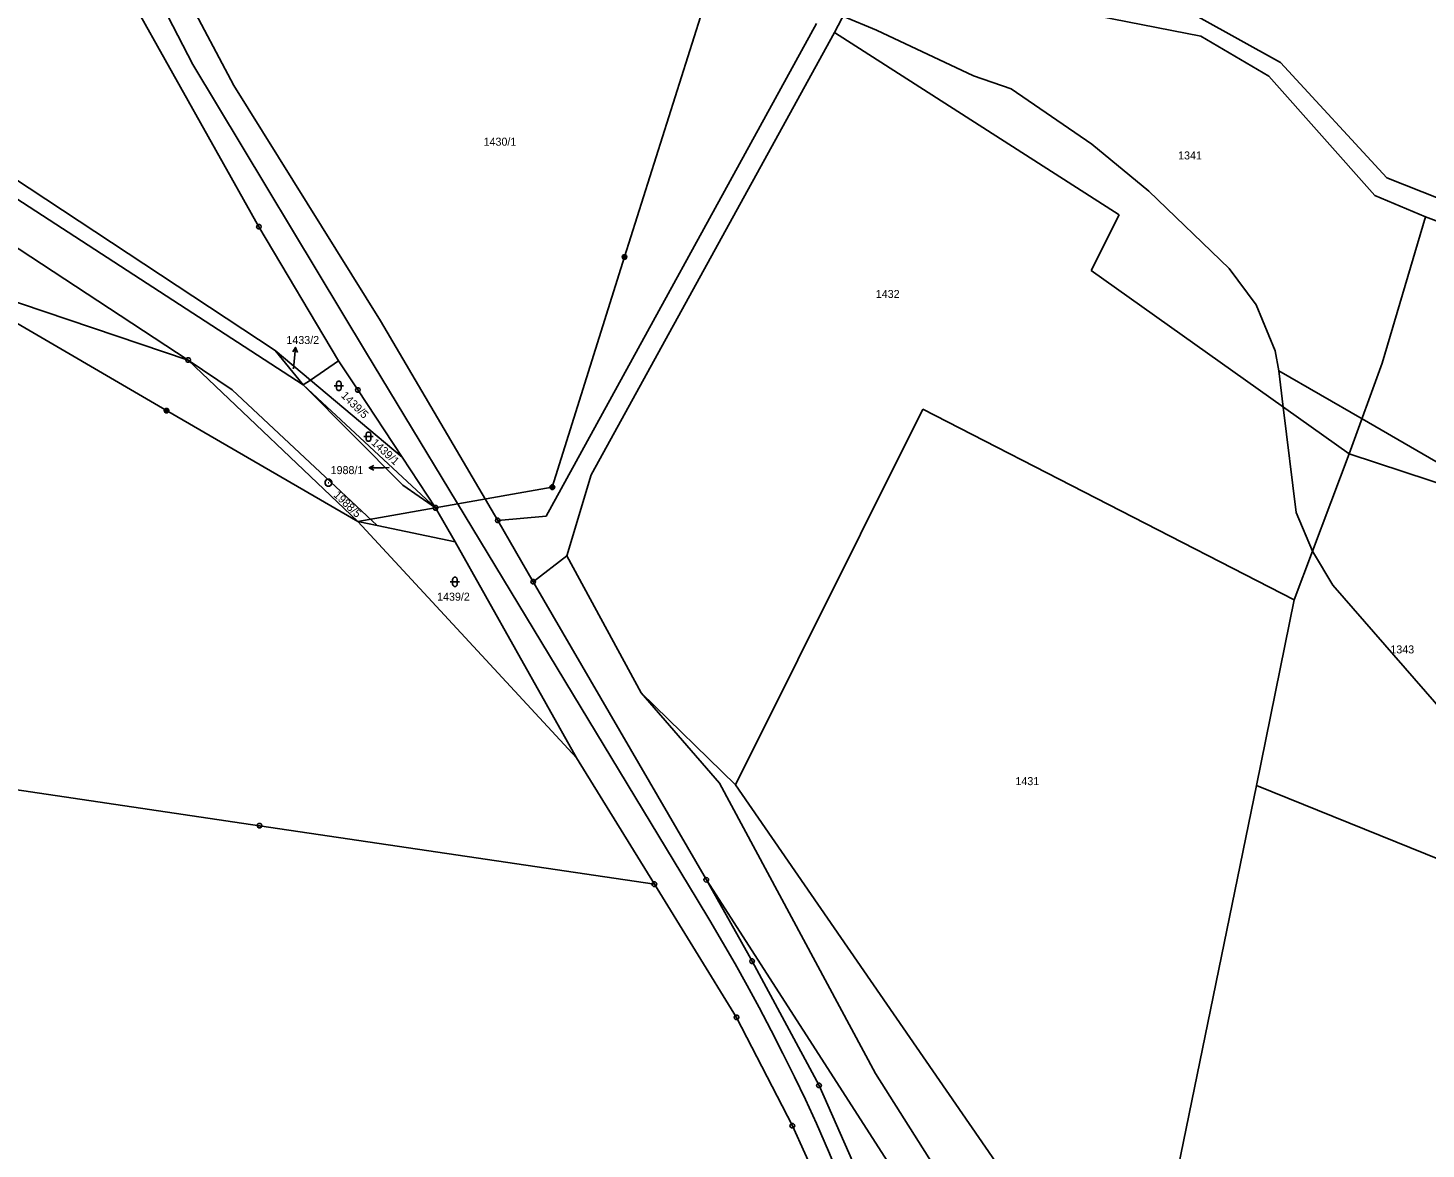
# Model space of a CAD drawing. Extents: x -789470 to -786707, y -1118640 to -1114455.
# Drawn here: x -787308.1 to -787011.1, y -1117950.7 to -1117712.5 of the extents above; entities that cross this region are included whole.
import ezdxf

# ---------------------------------------------------------------- set-up
doc = ezdxf.new("R2010")
doc.units = 0
for name, color, linetype in [('1', 7, 'Continuous'), ('11', 7, 'Continuous'), ('2', 7, 'Continuous'), ('3', 7, 'Continuous'), ('6', 7, 'Continuous'), ('7', 7, 'Continuous'), ('8', 7, 'Continuous')]:
    doc.layers.add(name, color=color, linetype=linetype)

msp = doc.modelspace()

# ---------------------------------------------------------------- linework, layer by layer
at = {"layer": '1'}
for p, q in [((-787264.39, -1117724.76), (-787281.5, -1117692.34)), ((-787291.42, -1117697.04), (-787259.05, -1117754.75)), ((-787130.82, -1117702.16), (-787136.77, -1117713.49)), ((-787058.93, -1117714.23), (-787093.33, -1117707.53)), ((-787140.62, -1117711.53), (-787198, -1117816.22)), ((-787059.5, -1117710.17), (-787042.03, -1117719.84)), ((-787188.44, -1117807.41), (-787136.77, -1117713.49)), ((-787136.77, -1117713.49), (-787076.27, -1117752.22)), ((-787044.49, -1117722.72), (-787058.93, -1117714.23)), ((-787042.03, -1117719.84), (-787019.38, -1117744.35)), ((-787021.94, -1117748.11), (-787044.49, -1117722.72)), ((-787255.59, -1117781.03), (-787341.85, -1117724.21)), ((-787233.24, -1117774.71), (-787264.39, -1117724.76)), ((-787249.62, -1117788.3), (-787339.28, -1117730.12)), ((-787334.34, -1117743.57), (-787274.1, -1117783.05)), ((-787019.38, -1117744.35), (-786937.83, -1117776.81)), ((-787011.2, -1117752.61), (-787021.94, -1117748.11)), ((-787076.27, -1117752.22), (-787082.23, -1117764.04)), ((-787020.37, -1117783.74), (-787011.2, -1117752.61)), ((-786970.08, -1117768.29), (-787011.2, -1117752.61)), ((-787259.05, -1117754.75), (-787242.15, -1117783.25)), ((-787329.24, -1117764.44), (-787274.1, -1117783.05)), ((-787082.23, -1117764.04), (-787027.4, -1117802.98)), ((-787208.31, -1117817.12), (-787233.24, -1117774.71)), ((-787274.1, -1117783.05), (-787264.76, -1117789.41)), ((-787274.1, -1117783.05), (-787238.04, -1117817.33)), ((-787255.59, -1117781.03), (-787249.62, -1117788.3)), ((-787248.13, -1117787.29), (-787255.59, -1117781.03)), ((-787242.15, -1117783.25), (-787248.13, -1117787.29)), ((-787242.15, -1117783.25), (-787238.02, -1117789.4)), ((-787027.4, -1117802.98), (-787020.37, -1117783.74)), ((-787248.13, -1117787.29), (-787249.62, -1117788.3)), ((-787228.5, -1117809.63), (-787249.62, -1117788.3)), ((-787221.52, -1117814.46), (-787249.62, -1117788.3)), ((-787228.62, -1117803.68), (-787248.13, -1117787.29)), ((-787264.76, -1117789.41), (-787233.93, -1117818.2)), ((-787238.02, -1117789.4), (-787228.62, -1117803.68)), ((-787157.82, -1117873.26), (-787118.02, -1117793.52)), ((-787118.02, -1117793.52), (-787039.1, -1117834.01)), ((-787228.62, -1117803.68), (-787221.52, -1117814.46)), ((-787039.1, -1117834.01), (-787027.4, -1117802.98)), ((-787027.4, -1117802.98), (-786983.7, -1117817.36)), ((-787221.52, -1117814.46), (-787228.5, -1117809.63)), ((-787193.66, -1117824.64), (-787188.44, -1117807.41)), ((-787221.52, -1117814.46), (-787217.39, -1117821.69)), ((-787191.61, -1117867.54), (-787238.04, -1117817.33)), ((-787238.04, -1117817.33), (-787233.93, -1117818.2)), ((-787233.93, -1117818.2), (-787217.39, -1117821.69)), ((-787198, -1117816.22), (-787208.31, -1117817.12)), ((-787200.76, -1117830.15), (-787208.31, -1117817.12)), ((-787217.39, -1117821.69), (-787191.61, -1117867.54)), ((-787200.76, -1117830.15), (-787193.66, -1117824.64)), ((-787193.66, -1117824.64), (-787177.84, -1117853.72)), ((-787163.99, -1117893.46), (-787200.76, -1117830.15)), ((-787047.08, -1117873.45), (-787039.1, -1117834.01)), ((-787177.84, -1117853.72), (-787161.21, -1117872.93)), ((-787177.84, -1117853.72), (-787157.82, -1117873.26)), ((-787175.04, -1117894.4), (-787191.61, -1117867.54)), ((-787342.81, -1117869.52), (-787258.93, -1117881.96)), ((-787161.21, -1117872.93), (-787128.04, -1117934.59)), ((-787157.82, -1117873.26), (-787077.39, -1117989.76)), ((-787071.15, -1117990.73), (-787047.08, -1117873.45)), ((-787047.08, -1117873.45), (-787004.56, -1117890.66)), ((-787175.04, -1117894.4), (-787258.93, -1117881.96)), ((-787157.56, -1117922.69), (-787175.04, -1117894.4)), ((-787163.99, -1117893.46), (-787091.23, -1118006.46)), ((-787154.27, -1117910.76), (-787163.99, -1117893.46)), ((-787140.05, -1117937.14), (-787154.27, -1117910.76)), ((-787145.72, -1117945.71), (-787157.56, -1117922.69)), ((-787128.04, -1117934.59), (-787083.58, -1118004.78)), ((-787131.85, -1117955.61), (-787140.05, -1117937.14)), ((-787135.71, -1117967.62), (-787145.72, -1117945.71))]:
    msp.add_line(p, q, dxfattribs=at)
at = {"layer": '11'}
for points in [[(-787134.96, -1117710.03), (-787127.81, -1117712.99), (-787107.23, -1117722.71), (-787099.24, -1117725.42), (-787082.09, -1117737.18), (-787070, -1117747.16), (-787052.94, -1117763.57), (-787047.15, -1117771.3), (-787043.1, -1117781.11), (-787042.34, -1117785.36)], [(-787042.34, -1117785.36), (-787024.68, -1117795.55), (-786991.12, -1117814.92), (-786984.15, -1117818.94), (-786981.58, -1117820.43), (-786936.16, -1117838.26), (-786913.37, -1117842.53), (-786900.27, -1117844.49), (-786842.47, -1117856.66), (-786829.42, -1117861.15), (-786821.6, -1117864.46), (-786814.71, -1117867.37), (-786798.67, -1117876.14)], [(-787042.34, -1117785.36), (-787041.4, -1117793.03), (-787038.67, -1117815.46), (-787035.18, -1117823.62), (-787035.02, -1117823.99), (-787030.91, -1117830.84), (-787006.87, -1117858.4), (-786998.03, -1117867.71), (-786979.04, -1117887.72), (-786975.32, -1117892.87), (-786971.98, -1117895.48), (-786967.44, -1117901.49), (-786952.89, -1117916.16), (-786931.6, -1117932.67), (-786922.44, -1117941.31), (-786915.44, -1117951.6)]]:
    msp.add_lwpolyline(points, dxfattribs=at)
at = {"layer": '3'}
for points in [[(-787243.08, -1117788.54), (-787241.81, -1117788.54), (-787241.08, -1117788.54)], [(-787236.79, -1117799.32), (-787235.52, -1117799.32), (-787234.79, -1117799.32)], [(-787218.41, -1117830.17), (-787217.14, -1117830.17), (-787216.41, -1117830.17)]]:
    msp.add_lwpolyline(points, dxfattribs=at)
for points in [[(-787242.58, -1117788.04), (-787242.48, -1117787.75), (-787242.23, -1117787.57), (-787241.92, -1117787.57), (-787241.67, -1117787.75), (-787241.57, -1117788.04), (-787241.57, -1117789.04), (-787241.67, -1117789.33), (-787241.92, -1117789.51), (-787242.23, -1117789.51), (-787242.48, -1117789.33), (-787242.58, -1117789.04)], [(-787236.29, -1117798.82), (-787236.19, -1117798.53), (-787235.94, -1117798.35), (-787235.63, -1117798.35), (-787235.38, -1117798.53), (-787235.28, -1117798.82), (-787235.28, -1117799.82), (-787235.38, -1117800.11), (-787235.63, -1117800.29), (-787235.94, -1117800.29), (-787236.19, -1117800.11), (-787236.29, -1117799.82)], [(-787217.91, -1117829.67), (-787217.81, -1117829.38), (-787217.56, -1117829.2), (-787217.25, -1117829.2), (-787217, -1117829.38), (-787216.9, -1117829.67), (-787216.9, -1117830.67), (-787217, -1117830.96), (-787217.25, -1117831.14), (-787217.56, -1117831.14), (-787217.81, -1117830.96), (-787217.91, -1117830.67)]]:
    msp.add_lwpolyline(points, close=True, dxfattribs=at)
at = {"layer": '6'}
for p, q in [((-787273.09, -1117720.29), (-787286.26, -1117694.67)), ((-787163.64, -1117705.03), (-787181.38, -1117761.15)), ((-787236.23, -1117781.6), (-787273.09, -1117720.29)), ((-787196.72, -1117810.06), (-787181.38, -1117761.15)), ((-787278.7, -1117793.79), (-787320.68, -1117769.26)), ((-787236.23, -1117781.6), (-787208.93, -1117826.64)), ((-787238.04, -1117817.33), (-787278.7, -1117793.79)), ((-787196.72, -1117810.06), (-787238.04, -1117817.33)), ((-787165.94, -1117897.62), (-787208.93, -1117826.64))]:
    msp.add_line(p, q, dxfattribs=at)
for points in [[(-787181.53, -1117760.67), (-787181.22, -1117760.67), (-787180.97, -1117760.85), (-787180.87, -1117761.14), (-787180.97, -1117761.43), (-787181.22, -1117761.61), (-787181.53, -1117761.61), (-787181.78, -1117761.43), (-787181.88, -1117761.14), (-787181.78, -1117760.85), (-787181.53, -1117760.67), (-787181.5, -1117760.71), (-787181.26, -1117760.71), (-787181.1, -1117760.79), (-787181.66, -1117760.79), (-787181.74, -1117760.87), (-787181.02, -1117760.87), (-787181.02, -1117760.95), (-787181.74, -1117760.95), (-787181.78, -1117761.03), (-787180.98, -1117761.03), (-787180.94, -1117761.11), (-787181.82, -1117761.11), (-787181.82, -1117761.19), (-787180.94, -1117761.19), (-787180.97, -1117761.27), (-787181.78, -1117761.27), (-787181.77, -1117761.35), (-787180.96, -1117761.35), (-787181.01, -1117761.43), (-787181.73, -1117761.43), (-787181.65, -1117761.51), (-787181.09, -1117761.51), (-787181.2, -1117761.59), (-787181.54, -1117761.59)], [(-787278.85, -1117793.31), (-787278.54, -1117793.31), (-787278.29, -1117793.49), (-787278.19, -1117793.78), (-787278.29, -1117794.07), (-787278.54, -1117794.25), (-787278.85, -1117794.25), (-787279.1, -1117794.07), (-787279.2, -1117793.78), (-787279.1, -1117793.49), (-787278.85, -1117793.31), (-787278.82, -1117793.35), (-787278.58, -1117793.35), (-787278.42, -1117793.43), (-787278.98, -1117793.43), (-787279.06, -1117793.51), (-787278.34, -1117793.51), (-787278.34, -1117793.59), (-787279.06, -1117793.59), (-787279.1, -1117793.67), (-787278.3, -1117793.67), (-787278.26, -1117793.75), (-787279.14, -1117793.75), (-787279.14, -1117793.83), (-787278.26, -1117793.83), (-787278.29, -1117793.91), (-787279.1, -1117793.91), (-787279.09, -1117793.99), (-787278.28, -1117793.99), (-787278.33, -1117794.07), (-787279.05, -1117794.07), (-787278.97, -1117794.15), (-787278.41, -1117794.15), (-787278.52, -1117794.23), (-787278.86, -1117794.23)], [(-787196.87, -1117809.58), (-787196.56, -1117809.58), (-787196.31, -1117809.76), (-787196.21, -1117810.05), (-787196.31, -1117810.34), (-787196.56, -1117810.52), (-787196.87, -1117810.52), (-787197.12, -1117810.34), (-787197.22, -1117810.05), (-787197.12, -1117809.76), (-787196.87, -1117809.58), (-787196.84, -1117809.62), (-787196.6, -1117809.62), (-787196.44, -1117809.7), (-787197, -1117809.7), (-787197.08, -1117809.78), (-787196.36, -1117809.78), (-787196.36, -1117809.86), (-787197.08, -1117809.86), (-787197.12, -1117809.94), (-787196.32, -1117809.94), (-787196.28, -1117810.02), (-787197.16, -1117810.02), (-787197.16, -1117810.1), (-787196.28, -1117810.1), (-787196.31, -1117810.18), (-787197.12, -1117810.18), (-787197.11, -1117810.26), (-787196.3, -1117810.26), (-787196.35, -1117810.34), (-787197.07, -1117810.34), (-787196.99, -1117810.42), (-787196.43, -1117810.42), (-787196.54, -1117810.5), (-787196.88, -1117810.5)], [(-787165.94, -1117897.62), (-787163.23, -1117902.12), (-787160.54, -1117906.71), (-787157.89, -1117911.34), (-787155.34, -1117915.93), (-787152.79, -1117920.62), (-787150.22, -1117925.49), (-787147.71, -1117930.38), (-787145.25, -1117935.31), (-787142.93, -1117940.11)], [(-787142.93, -1117940.11), (-787140.59, -1117945.22), (-787138.02, -1117951.09), (-787135.54, -1117957), (-787133.44, -1117962.22), (-787131.39, -1117967.48), (-787129.15, -1117973.53), (-787126.99, -1117979.62), (-787124.94, -1117985.74), (-787123.22, -1117991.12)]]:
    msp.add_lwpolyline(points, dxfattribs=at)
at = {"layer": '7'}
for p, q in [((-787251.26, -1117780.38), (-787251.55, -1117783.37)), ((-787251.7, -1117784.93), (-787251.55, -1117783.37)), ((-787235.62, -1117805.94), (-787232.62, -1117805.92)), ((-787231.4, -1117805.91), (-787232.62, -1117805.92))]:
    msp.add_line(p, q, dxfattribs=at)
for points in [[(-787251.86, -1117781.33), (-787251.26, -1117780.38), (-787250.86, -1117781.43)], [(-787234.62, -1117806.43), (-787235.62, -1117805.94), (-787234.62, -1117805.43)]]:
    msp.add_lwpolyline(points, dxfattribs=at)
at = {"layer": '8'}
for p, q in [((-787259.17, -1117754.75), (-787258.93, -1117754.75)), ((-787274.22, -1117783.05), (-787273.98, -1117783.05)), ((-787238.14, -1117789.4), (-787237.9, -1117789.4)), ((-787244.33, -1117809.1), (-787244.23, -1117809.1)), ((-787221.64, -1117814.46), (-787221.4, -1117814.46)), ((-787208.43, -1117817.12), (-787208.19, -1117817.12)), ((-787200.88, -1117830.15), (-787200.64, -1117830.15)), ((-787259.05, -1117881.96), (-787258.81, -1117881.96)), ((-787175.16, -1117894.4), (-787174.92, -1117894.4)), ((-787164.11, -1117893.44), (-787163.87, -1117893.48)), ((-787154.39, -1117910.76), (-787154.15, -1117910.76)), ((-787157.68, -1117922.69), (-787157.44, -1117922.69)), ((-787140.17, -1117937.14), (-787139.93, -1117937.14)), ((-787145.84, -1117945.71), (-787145.6, -1117945.71))]:
    msp.add_line(p, q, dxfattribs=at)
for points in [[(-787258.9, -1117754.27), (-787258.65, -1117754.45), (-787258.55, -1117754.74), (-787258.65, -1117755.03), (-787258.9, -1117755.21), (-787259.21, -1117755.21), (-787259.46, -1117755.03), (-787259.56, -1117754.74), (-787259.46, -1117754.45), (-787259.21, -1117754.27)], [(-787273.95, -1117782.57), (-787273.7, -1117782.75), (-787273.6, -1117783.04), (-787273.7, -1117783.33), (-787273.95, -1117783.51), (-787274.26, -1117783.51), (-787274.51, -1117783.33), (-787274.61, -1117783.04), (-787274.51, -1117782.75), (-787274.26, -1117782.57)], [(-787237.87, -1117788.92), (-787237.62, -1117789.1), (-787237.52, -1117789.39), (-787237.62, -1117789.68), (-787237.87, -1117789.86), (-787238.18, -1117789.86), (-787238.43, -1117789.68), (-787238.53, -1117789.39), (-787238.43, -1117789.1), (-787238.18, -1117788.92)], [(-787244.09, -1117808.38), (-787243.75, -1117808.57), (-787243.56, -1117808.91), (-787243.56, -1117809.3), (-787243.75, -1117809.64), (-787244.09, -1117809.83), (-787244.48, -1117809.83), (-787244.82, -1117809.64), (-787245.01, -1117809.3), (-787245.01, -1117808.91), (-787244.82, -1117808.57), (-787244.48, -1117808.38)], [(-787221.37, -1117813.98), (-787221.12, -1117814.16), (-787221.02, -1117814.45), (-787221.12, -1117814.74), (-787221.37, -1117814.92), (-787221.68, -1117814.92), (-787221.93, -1117814.74), (-787222.03, -1117814.45), (-787221.93, -1117814.16), (-787221.68, -1117813.98)], [(-787208.16, -1117816.64), (-787207.91, -1117816.82), (-787207.81, -1117817.11), (-787207.91, -1117817.4), (-787208.16, -1117817.58), (-787208.47, -1117817.58), (-787208.72, -1117817.4), (-787208.82, -1117817.11), (-787208.72, -1117816.82), (-787208.47, -1117816.64)], [(-787200.61, -1117829.67), (-787200.36, -1117829.85), (-787200.26, -1117830.14), (-787200.36, -1117830.43), (-787200.61, -1117830.61), (-787200.92, -1117830.61), (-787201.17, -1117830.43), (-787201.27, -1117830.14), (-787201.17, -1117829.85), (-787200.92, -1117829.67)], [(-787258.78, -1117881.48), (-787258.53, -1117881.66), (-787258.43, -1117881.95), (-787258.53, -1117882.24), (-787258.78, -1117882.42), (-787259.09, -1117882.42), (-787259.34, -1117882.24), (-787259.44, -1117881.95), (-787259.34, -1117881.66), (-787259.09, -1117881.48)], [(-787163.76, -1117893.01), (-787163.54, -1117893.24), (-787163.5, -1117893.54), (-787163.65, -1117893.81), (-787163.92, -1117893.94), (-787164.23, -1117893.88), (-787164.44, -1117893.66), (-787164.49, -1117893.36), (-787164.34, -1117893.09), (-787164.06, -1117892.96)], [(-787174.89, -1117893.92), (-787174.64, -1117894.1), (-787174.54, -1117894.39), (-787174.64, -1117894.68), (-787174.89, -1117894.86), (-787175.2, -1117894.86), (-787175.45, -1117894.68), (-787175.55, -1117894.39), (-787175.45, -1117894.1), (-787175.2, -1117893.92)], [(-787154.12, -1117910.28), (-787153.87, -1117910.46), (-787153.77, -1117910.75), (-787153.87, -1117911.04), (-787154.12, -1117911.22), (-787154.43, -1117911.22), (-787154.68, -1117911.04), (-787154.78, -1117910.75), (-787154.68, -1117910.46), (-787154.43, -1117910.28)], [(-787157.41, -1117922.21), (-787157.16, -1117922.39), (-787157.06, -1117922.68), (-787157.16, -1117922.97), (-787157.41, -1117923.15), (-787157.72, -1117923.15), (-787157.97, -1117922.97), (-787158.07, -1117922.68), (-787157.97, -1117922.39), (-787157.72, -1117922.21)], [(-787139.9, -1117936.66), (-787139.65, -1117936.84), (-787139.55, -1117937.13), (-787139.65, -1117937.42), (-787139.9, -1117937.6), (-787140.21, -1117937.6), (-787140.46, -1117937.42), (-787140.56, -1117937.13), (-787140.46, -1117936.84), (-787140.21, -1117936.66)], [(-787145.57, -1117945.23), (-787145.32, -1117945.41), (-787145.22, -1117945.7), (-787145.32, -1117945.99), (-787145.57, -1117946.17), (-787145.88, -1117946.17), (-787146.13, -1117945.99), (-787146.23, -1117945.7), (-787146.13, -1117945.41), (-787145.88, -1117945.23)]]:
    msp.add_lwpolyline(points, close=True, dxfattribs=at)

# ---------------------------------------------------------------- texts
at = {"layer": '2'}
for s, height, p in [('1430/1', 1.7, (-787211.32, -1117737.52)), ('1341', 1.7, (-787063.76, -1117740.44)), ('1432', 1.7, (-787127.99, -1117769.86)), ('1433/2', 0.1, (-787251.94, -1117784.93)), ('1988/1', 0.1, (-787231.6, -1117805.91)), ('1439/2', 1.7, (-787221.2, -1117834.17)), ('1343', 1.7, (-787018.66, -1117845.37)), ('1431', 1.7, (-787098.32, -1117873.35))]:
    msp.add_text(s, height=height, dxfattribs=at).set_placement(p)
for s, rotation, p in [('1439/5', 315.5852, (-787241.74, -1117790.76)), ('1439/1', 317.5905, (-787235.31, -1117800.82)), ('1988/5', 316.4446, (-787243.32, -1117811.88))]:
    msp.add_text(s, height=1.7, rotation=rotation, dxfattribs=at).set_placement(p)
at = {"layer": '7'}
for s, p in [('1433/2', (-787253.22, -1117779.65)), ('1988/1', (-787243.82, -1117807.28))]:
    msp.add_text(s, height=1.7, dxfattribs=at).set_placement(p)

doc.saveas('drawing.dxf')
